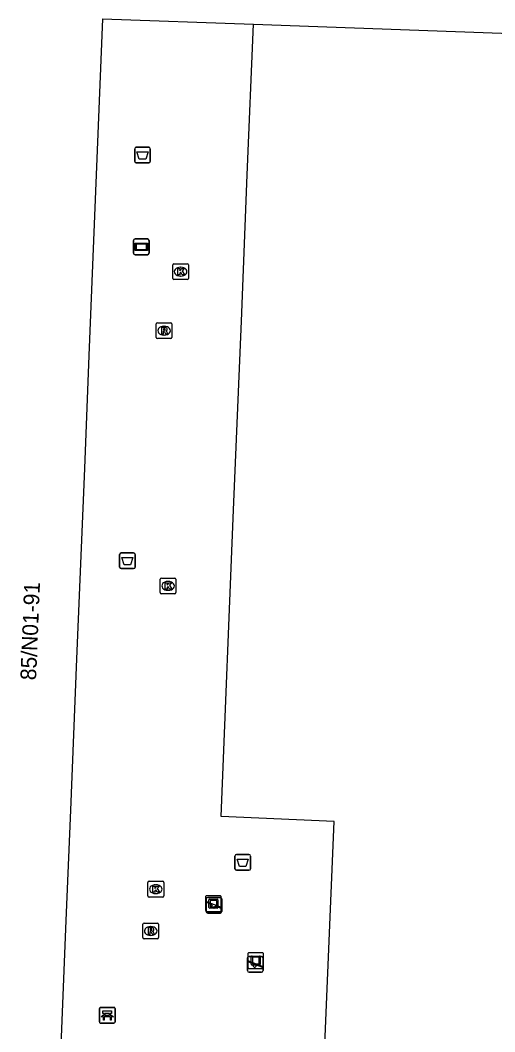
# Model space of a CAD drawing. Extents: x 160891 to 161384, y 386490 to 386907.
# Drawn here: x 161156 to 161186.2, y 386769.6 to 386833.9 of the extents above; entities that cross this region are included whole.
import ezdxf

# ---------------------------------------------------------------- set-up
doc = ezdxf.new("R2010")
doc.units = 0
for name, color, linetype in [('IMGEO_Afvalbak', 7, 'Continuous'), ('IMGEO_Bank', 7, 'Continuous'), ('IMGEO_Kolk', 7, 'Continuous'), ('IMGEO_Kunstobject', 7, 'Continuous'), ('IMGEO_Pand', 7, 'Continuous'), ('IMGEO_Pand_nummerreeks', 7, 'Continuous'), ('IMGEO_Reclamebord', 7, 'Continuous'), ('IMGEO_Rioolput', 7, 'Continuous'), ('IMGEO_Speelvoorziening', 7, 'Continuous'), ('IMGEO_Voetpad_open', 7, 'Continuous')]:
    doc.layers.add(name, color=color, linetype=linetype)

msp = doc.modelspace()

# ---------------------------------------------------------------- linework, layer by layer
at = {"layer": 'IMGEO_Afvalbak'}
for p, q in [((161163.42, 386825.803), (161164.21, 386825.803)), ((161164.21, 386825.803), (161163.42, 386825.803)), ((161163.32, 386824.903), (161163.32, 386825.703)), ((161163.32, 386825.703), (161163.32, 386824.903)), ((161164.31, 386825.703), (161164.31, 386824.903)), ((161164.31, 386824.903), (161164.31, 386825.703)), ((161164.21, 386824.803), (161163.42, 386824.803)), ((161163.42, 386824.803), (161164.21, 386824.803)), ((161162.36, 386799.115), (161162.36, 386799.915)), ((161162.36, 386799.915), (161162.36, 386799.115)), ((161162.46, 386800.015), (161163.25, 386800.015)), ((161163.25, 386800.015), (161162.46, 386800.015)), ((161163.35, 386799.915), (161163.35, 386799.115)), ((161163.35, 386799.115), (161163.35, 386799.915)), ((161163.25, 386799.015), (161162.46, 386799.015)), ((161162.46, 386799.015), (161163.25, 386799.015)), ((161169.786, 386780.845), (161170.576, 386780.845)), ((161170.576, 386780.845), (161169.786, 386780.845)), ((161169.686, 386779.945), (161169.686, 386780.745)), ((161169.686, 386780.745), (161169.686, 386779.945)), ((161170.676, 386780.745), (161170.676, 386779.945)), ((161170.676, 386779.945), (161170.676, 386780.745)), ((161170.576, 386779.845), (161169.786, 386779.845)), ((161169.786, 386779.845), (161170.576, 386779.845))]:
    msp.add_line(p, q, dxfattribs=at)
for points in [[(161163.463, 386825.517), (161164.167, 386825.517), (161164.018, 386825.047), (161163.612, 386825.047), (161163.463, 386825.517)], [(161162.503, 386799.729), (161163.207, 386799.729), (161163.058, 386799.259), (161162.652, 386799.259), (161162.503, 386799.729)], [(161169.829, 386780.559), (161170.533, 386780.559), (161170.384, 386780.089), (161169.978, 386780.089), (161169.829, 386780.559)]]:
    msp.add_lwpolyline(points, dxfattribs=at)
for centre, start, end in [((161163.42, 386825.703), 90, 180), ((161163.42, 386825.703), 90, 180), ((161164.21, 386825.703), 0, 90), ((161164.21, 386825.703), 360, 90), ((161163.42, 386824.903), 180, 270), ((161163.42, 386824.903), 180, 270), ((161164.21, 386824.903), 270, 0), ((161164.21, 386824.903), 270, 0), ((161162.46, 386799.915), 90, 180), ((161162.46, 386799.915), 90, 180), ((161163.25, 386799.915), 0, 90), ((161163.25, 386799.915), 360, 90), ((161162.46, 386799.115), 180, 270), ((161162.46, 386799.115), 180, 270), ((161163.25, 386799.115), 270, 0), ((161163.25, 386799.115), 270, 0), ((161169.786, 386780.745), 90, 180), ((161169.786, 386780.745), 90, 180), ((161170.576, 386780.745), 0, 90), ((161170.576, 386780.745), 360, 90), ((161169.786, 386779.945), 180, 270), ((161169.786, 386779.945), 180, 270), ((161170.576, 386779.945), 270, 0), ((161170.576, 386779.945), 270, 0)]:
    msp.add_arc(centre, 0.1, start, end, dxfattribs=at)
at = {"layer": 'IMGEO_Bank'}
for p, q in [((161161.148, 386771.132), (161161.989, 386771.132)), ((161161.989, 386771.132), (161161.148, 386771.132)), ((161161.073, 386770.207), (161161.073, 386771.048)), ((161161.073, 386771.048), (161161.073, 386770.207)), ((161161.77, 386770.53), (161161.377, 386770.53)), ((161161.382, 386770.638), (161161.382, 386770.744)), ((161161.426, 386770.744), (161161.426, 386770.638)), ((161161.714, 386770.75), (161161.432, 386770.75)), ((161161.432, 386770.632), (161161.714, 386770.632)), ((161161.72, 386770.638), (161161.72, 386770.744)), ((161161.764, 386770.744), (161161.764, 386770.638)), ((161162.073, 386771.057), (161162.073, 386770.216)), ((161162.073, 386770.216), (161162.073, 386771.057)), ((161161.998, 386770.132), (161161.157, 386770.132)), ((161161.157, 386770.132), (161161.998, 386770.132))]:
    msp.add_line(p, q, dxfattribs=at)
for points in [[(161161.32, 386770.53), (161161.178, 386770.53), (161161.29, 386770.632), (161161.376, 386770.632)], [(161161.376, 386770.75), (161161.29, 386770.75), (161161.29, 386770.911), (161161.853, 386770.911), (161161.853, 386770.75), (161161.77, 386770.75)], [(161161.37, 386770.523), (161161.37, 386770.316), (161161.327, 386770.316), (161161.327, 386770.523)], [(161161.77, 386770.632), (161161.853, 386770.632), (161161.965, 386770.53), (161161.826, 386770.53)], [(161161.82, 386770.523), (161161.82, 386770.316), (161161.776, 386770.316), (161161.776, 386770.523)]]:
    msp.add_lwpolyline(points, dxfattribs=at)
for centre, radius, start, end in [((161161.151, 386771.054), 0.0779, 92.4484, 184.28452), ((161161.151, 386771.054), 0.0779, 92.4484, 184.28452), ((161161.995, 386771.054), 0.0779, 2.4484, 94.28452), ((161161.995, 386771.054), 0.0779, 2.4484, 94.28452), ((161161.32, 386770.523), 0.00671, 2.89567, 87.10433), ((161161.377, 386770.523), 0.00671, 92.89567, 177.10433), ((161161.375, 386770.743), 0.00671, 2.89567, 87.10433), ((161161.375, 386770.639), 0.00671, 272.89567, 357.10433), ((161161.432, 386770.743), 0.00671, 92.89567, 177.10433), ((161161.432, 386770.639), 0.00671, 182.89567, 267.10433), ((161161.714, 386770.743), 0.00671, 2.89567, 87.10433), ((161161.714, 386770.639), 0.00671, 272.89567, 357.10433), ((161161.771, 386770.743), 0.00671, 92.89567, 177.10433), ((161161.771, 386770.639), 0.00671, 182.89567, 267.10433), ((161161.769, 386770.523), 0.00671, 2.89567, 87.10433), ((161161.826, 386770.523), 0.00671, 92.89567, 177.10433), ((161161.151, 386770.21), 0.0779, 182.4484, 274.28452), ((161161.151, 386770.21), 0.0779, 182.4484, 274.28452), ((161161.995, 386770.21), 0.0779, 272.4484, 4.28452), ((161161.995, 386770.21), 0.0779, 272.4484, 4.28452)]:
    msp.add_arc(centre, radius, start, end, dxfattribs=at)
at = {"layer": 'IMGEO_Kolk'}
for p, q in [((161165.734, 386817.465), (161165.734, 386818.317)), ((161165.809, 386818.391), (161166.661, 386818.391)), ((161166.222, 386818.171), (161166.247, 386818.171)), ((161166.735, 386818.317), (161166.735, 386817.465)), ((161166.245, 386817.611), (161166.22, 386817.611)), ((161166.661, 386817.391), (161165.809, 386817.391)), ((161164.941, 386797.493), (161164.941, 386798.345)), ((161165.016, 386798.419), (161165.868, 386798.419)), ((161165.429, 386798.199), (161165.454, 386798.199)), ((161165.942, 386798.345), (161165.942, 386797.493)), ((161165.452, 386797.639), (161165.427, 386797.639)), ((161165.868, 386797.419), (161165.016, 386797.419)), ((161164.159, 386778.217), (161164.159, 386779.069)), ((161164.234, 386779.143), (161165.086, 386779.143)), ((161164.647, 386778.923), (161164.672, 386778.923)), ((161165.16, 386779.069), (161165.16, 386778.217)), ((161164.67, 386778.363), (161164.645, 386778.363)), ((161165.086, 386778.143), (161164.234, 386778.143))]:
    msp.add_line(p, q, dxfattribs=at)
for points in [[(161165.734, 386817.465), (161165.734, 386818.317)], [(161165.809, 386818.391), (161166.661, 386818.391)], [(161166.055, 386818.091), (161166.178, 386818.091), (161166.178, 386817.94), (161166.308, 386818.091), (161166.472, 386818.091), (161166.326, 386817.94), (161166.479, 386817.691), (161166.327, 386817.691), (161166.242, 386817.855), (161166.178, 386817.788), (161166.178, 386817.691), (161166.055, 386817.691), (161166.055, 386818.091)], [(161166.735, 386818.317), (161166.735, 386817.465)], [(161166.661, 386817.391), (161165.809, 386817.391)], [(161164.941, 386797.493), (161164.941, 386798.345)], [(161165.016, 386798.419), (161165.868, 386798.419)], [(161165.942, 386798.345), (161165.942, 386797.493)], [(161165.262, 386798.119), (161165.385, 386798.119), (161165.385, 386797.968), (161165.515, 386798.119), (161165.679, 386798.119), (161165.533, 386797.968), (161165.686, 386797.719), (161165.534, 386797.719), (161165.449, 386797.883), (161165.385, 386797.816), (161165.385, 386797.719), (161165.262, 386797.719), (161165.262, 386798.119)], [(161165.868, 386797.419), (161165.016, 386797.419)], [(161164.159, 386778.217), (161164.159, 386779.069)], [(161164.234, 386779.143), (161165.086, 386779.143)], [(161164.48, 386778.843), (161164.603, 386778.843), (161164.603, 386778.692), (161164.733, 386778.843), (161164.897, 386778.843), (161164.751, 386778.692), (161164.904, 386778.443), (161164.752, 386778.443), (161164.667, 386778.607), (161164.603, 386778.54), (161164.603, 386778.443), (161164.48, 386778.443), (161164.48, 386778.843)], [(161165.16, 386779.069), (161165.16, 386778.217)], [(161165.086, 386778.143), (161164.234, 386778.143)]]:
    msp.add_lwpolyline(points, dxfattribs=at)
for centre, start, end in [((161165.811, 386818.315), 91.55205, 178.44795), ((161165.811, 386818.315), 91.55205, 178.44795), ((161166.659, 386818.315), 1.55205, 88.44795), ((161166.659, 386818.315), 1.55205, 88.44795), ((161165.811, 386817.467), 181.55205, 268.44795), ((161165.811, 386817.467), 181.55205, 268.44795), ((161166.659, 386817.467), 271.55205, 358.44795), ((161166.659, 386817.467), 271.55205, 358.44795), ((161165.018, 386798.343), 91.55205, 178.44795), ((161165.018, 386798.343), 91.55205, 178.44795), ((161165.866, 386798.343), 1.55205, 88.44795), ((161165.866, 386798.343), 1.55205, 88.44795), ((161165.018, 386797.495), 181.55205, 268.44795), ((161165.018, 386797.495), 181.55205, 268.44795), ((161165.866, 386797.495), 271.55205, 358.44795), ((161165.866, 386797.495), 271.55205, 358.44795), ((161164.236, 386779.067), 91.55205, 178.44795), ((161164.236, 386779.067), 91.55205, 178.44795), ((161165.084, 386779.067), 1.55205, 88.44795), ((161165.084, 386779.067), 1.55205, 88.44795), ((161164.236, 386778.219), 181.55205, 268.44795), ((161164.236, 386778.219), 181.55205, 268.44795), ((161165.084, 386778.219), 271.55205, 358.44795), ((161165.084, 386778.219), 271.55205, 358.44795)]:
    msp.add_arc(centre, 0.0765, start, end, dxfattribs=at)
for centre, major_axis, ratio, start_param, end_param in [((161166.221, 386817.891), (-0.387, 0.002), 0.722429, 4.712389, 7.853982), ((161166.246, 386817.891), (-0.39, 0.002), 0.717154, 1.570796, 4.712389), ((161165.428, 386797.919), (-0.387, 0.002), 0.722429, 4.712389, 7.853982), ((161165.453, 386797.919), (-0.39, 0.002), 0.717154, 1.570796, 4.712389), ((161164.646, 386778.643), (-0.387, 0.002), 0.722429, 4.712389, 7.853982), ((161164.671, 386778.643), (-0.39, 0.002), 0.717154, 1.570796, 4.712389)]:
    msp.add_ellipse(centre, major_axis=major_axis, ratio=ratio, start_param=start_param, end_param=end_param, dxfattribs=at)
at = {"layer": 'IMGEO_Kunstobject'}
for p, q in [((161168.739, 386778.223), (161167.898, 386778.223)), ((161168.739, 386778.223), (161167.898, 386778.223)), ((161167.823, 386778.139), (161167.823, 386777.298)), ((161167.823, 386778.139), (161167.823, 386777.298)), ((161168.037, 386777.487), (161168.037, 386777.961)), ((161168.087, 386778.011), (161168.561, 386778.011)), ((161168.117, 386777.911), (161168.117, 386777.537)), ((161168.511, 386777.931), (161168.137, 386777.931)), ((161168.531, 386777.537), (161168.531, 386777.911)), ((161168.611, 386777.961), (161168.611, 386777.487)), ((161168.823, 386777.307), (161168.823, 386778.148)), ((161168.823, 386777.307), (161168.823, 386778.148)), ((161167.907, 386777.223), (161168.748, 386777.223)), ((161167.907, 386777.223), (161168.748, 386777.223)), ((161168.561, 386777.437), (161168.087, 386777.437)), ((161168.137, 386777.517), (161168.511, 386777.517)), ((161170.514, 386774.521), (161170.514, 386773.68)), ((161170.514, 386774.521), (161170.514, 386773.68)), ((161171.43, 386774.605), (161170.589, 386774.605)), ((161171.43, 386774.605), (161170.589, 386774.605)), ((161170.728, 386773.869), (161170.728, 386774.343)), ((161170.778, 386774.393), (161171.252, 386774.393)), ((161171.302, 386774.343), (161171.302, 386773.869)), ((161171.514, 386773.689), (161171.514, 386774.53)), ((161171.514, 386773.689), (161171.514, 386774.53)), ((161171.252, 386773.819), (161170.778, 386773.819)), ((161170.808, 386774.293), (161170.808, 386773.919)), ((161171.202, 386774.313), (161170.828, 386774.313)), ((161170.828, 386773.899), (161171.202, 386773.899)), ((161171.222, 386773.919), (161171.222, 386774.293)), ((161170.598, 386773.605), (161171.439, 386773.605)), ((161170.598, 386773.605), (161171.439, 386773.605))]:
    msp.add_line(p, q, dxfattribs=at)
for centre, radius, start, end in [((161167.901, 386778.145), 0.0779, 92.4484, 184.28452), ((161167.901, 386778.145), 0.0779, 92.4484, 184.28452), ((161168.745, 386778.145), 0.0779, 2.4484, 94.28452), ((161168.745, 386778.145), 0.0779, 2.4484, 94.28452), ((161168.087, 386777.961), 0.05, 90, 180), ((161168.137, 386777.911), 0.02, 90, 180), ((161168.511, 386777.911), 0.02, 360, 90), ((161168.561, 386777.961), 0.05, 360, 90), ((161167.901, 386777.301), 0.0779, 182.4484, 274.28452), ((161167.901, 386777.301), 0.0779, 182.4484, 274.28452), ((161168.087, 386777.487), 0.05, 180, 270), ((161168.137, 386777.537), 0.02, 180, 270), ((161168.511, 386777.537), 0.02, 270, 0), ((161168.561, 386777.487), 0.05, 270, 0), ((161168.745, 386777.301), 0.0779, 272.4484, 4.28452), ((161168.745, 386777.301), 0.0779, 272.4484, 4.28452), ((161170.592, 386774.527), 0.0779, 92.4484, 184.28452), ((161170.592, 386774.527), 0.0779, 92.4484, 184.28452), ((161170.778, 386774.343), 0.05, 90, 180), ((161171.252, 386774.343), 0.05, 360, 90), ((161171.436, 386774.527), 0.0779, 2.4484, 94.28452), ((161171.436, 386774.527), 0.0779, 2.4484, 94.28452), ((161170.778, 386773.869), 0.05, 180, 270), ((161170.828, 386774.293), 0.02, 90, 180), ((161170.828, 386773.919), 0.02, 180, 270), ((161171.202, 386774.293), 0.02, 360, 90), ((161171.202, 386773.919), 0.02, 270, 0), ((161171.252, 386773.869), 0.05, 270, 0), ((161170.592, 386773.683), 0.0779, 182.4484, 274.28452), ((161170.592, 386773.683), 0.0779, 182.4484, 274.28452), ((161171.436, 386773.683), 0.0779, 272.4484, 4.28452), ((161171.436, 386773.683), 0.0779, 272.4484, 4.28452)]:
    msp.add_arc(centre, radius, start, end, dxfattribs=at)
at = {"layer": 'IMGEO_Pand'}
for points in [[(161161.282, 386833.963), (161160.709, 386819.875), (161160.411, 386812.554), (161160.119, 386805.384), (161159.627, 386793.285), (161159.236, 386783.673), (161158.95, 386776.656), (161158.648, 386769.233), (161158.228, 386758.915)], [(161173.519, 386722.968), (161174.331, 386742.954), (161174.605, 386749.514), (161174.625, 386750), (161174.808, 386754.38), (161175.112, 386761.653), (161175.409, 386768.77), (161176.001, 386782.954), (161168.81, 386783.258), (161169.606, 386802.752), (161170.096, 386814.751), (161170.475, 386824.04), (161170.867, 386833.628)], [(161170.867, 386833.628), (161190.117, 386832.93), (161199.627, 386832.585), (161199.621, 386832.448)]]:
    msp.add_lwpolyline(points, dxfattribs=at)
at = {"layer": 'IMGEO_Reclamebord'}
for p, q in [((161163.239, 386819.071), (161163.239, 386819.871)), ((161163.239, 386819.871), (161163.239, 386819.071)), ((161163.339, 386819.971), (161164.129, 386819.971)), ((161164.129, 386819.971), (161163.339, 386819.971)), ((161164.229, 386819.871), (161164.229, 386819.071)), ((161164.229, 386819.071), (161164.229, 386819.871)), ((161164.129, 386818.971), (161163.339, 386818.971)), ((161163.339, 386818.971), (161164.129, 386818.971))]:
    msp.add_line(p, q, dxfattribs=at)
for points in [[(161163.34, 386819.703), (161164.128, 386819.703), (161164.128, 386819.239), (161163.34, 386819.239), (161163.34, 386819.703)], [(161163.405, 386819.638), (161163.405, 386819.304), (161164.063, 386819.304), (161164.063, 386819.638), (161163.405, 386819.638)]]:
    msp.add_lwpolyline(points, dxfattribs=at)
for centre, start, end in [((161163.339, 386819.871), 90, 180), ((161163.339, 386819.871), 90, 180), ((161164.129, 386819.871), 0, 90), ((161164.129, 386819.871), 360, 90), ((161163.339, 386819.071), 180, 270), ((161163.339, 386819.071), 180, 270), ((161164.129, 386819.071), 270, 0), ((161164.129, 386819.071), 270, 0)]:
    msp.add_arc(centre, 0.1, start, end, dxfattribs=at)
at = {"layer": 'IMGEO_Rioolput'}
for p, q in [((161164.687, 386813.716), (161164.687, 386814.568)), ((161164.762, 386814.642), (161165.614, 386814.642)), ((161165.175, 386814.422), (161165.2, 386814.422)), ((161165.688, 386814.568), (161165.688, 386813.716)), ((161165.614, 386813.642), (161164.762, 386813.642)), ((161165.198, 386813.862), (161165.173, 386813.862)), ((161163.839, 386775.562), (161163.839, 386776.414)), ((161163.914, 386776.488), (161164.766, 386776.488)), ((161164.327, 386776.268), (161164.352, 386776.268)), ((161164.84, 386776.414), (161164.84, 386775.562)), ((161164.35, 386775.708), (161164.325, 386775.708)), ((161164.766, 386775.488), (161163.914, 386775.488))]:
    msp.add_line(p, q, dxfattribs=at)
for points in [[(161164.687, 386813.716), (161164.687, 386814.568)], [(161164.762, 386814.642), (161165.614, 386814.642)], [(161165.276, 386814.34), (161165.024, 386814.342), (161165.024, 386813.942)], [(161165.202, 386814.261), (161165.148, 386814.261), (161165.148, 386814.18)], [(161165.688, 386814.568), (161165.688, 386813.716)], [(161165.614, 386813.642), (161164.762, 386813.642)], [(161165.024, 386813.942), (161165.148, 386813.942), (161165.148, 386814.104), (161165.159, 386814.104)], [(161165.148, 386814.18), (161165.2, 386814.18)], [(161165.206, 386814.075), (161165.277, 386813.942), (161165.417, 386813.942), (161165.352, 386814.068)], [(161163.839, 386775.562), (161163.839, 386776.414)], [(161163.914, 386776.488), (161164.766, 386776.488)], [(161164.84, 386776.414), (161164.84, 386775.562)], [(161164.428, 386776.186), (161164.176, 386776.188), (161164.176, 386775.788)], [(161164.176, 386775.788), (161164.3, 386775.788), (161164.3, 386775.95), (161164.311, 386775.95)], [(161164.354, 386776.107), (161164.3, 386776.107), (161164.3, 386776.026)], [(161164.3, 386776.026), (161164.352, 386776.026)], [(161164.358, 386775.921), (161164.429, 386775.788), (161164.569, 386775.788), (161164.504, 386775.914)], [(161164.766, 386775.488), (161163.914, 386775.488)]]:
    msp.add_lwpolyline(points, dxfattribs=at)
for centre, radius, start, end in [((161164.764, 386814.566), 0.0765, 91.55205, 178.44795), ((161164.764, 386814.566), 0.0765, 91.55205, 178.44795), ((161165.208, 386814.165), 0.0964, 77.00612, 93.18647), ((161165.222, 386814.222), 0.0378, 276.66336, 79.67722), ((161165.275, 386814.23), 0.109, 350.36119, 89.41601), ((161165.273, 386814.23), 0.112, 277.58423, 350.98172), ((161165.612, 386814.566), 0.0765, 1.55205, 88.44795), ((161165.612, 386814.566), 0.0765, 1.55205, 88.44795), ((161164.764, 386813.718), 0.0765, 181.55205, 268.44795), ((161164.764, 386813.718), 0.0765, 181.55205, 268.44795), ((161165.158, 386814.051), 0.0533, 26.02933, 88.69889), ((161165.184, 386814.369), 0.19, 274.7715, 282.96867), ((161165.257, 386814.015), 0.108, 29.51342, 73.79051), ((161165.612, 386813.718), 0.0765, 271.55205, 358.44795), ((161165.612, 386813.718), 0.0765, 271.55205, 358.44795), ((161163.916, 386776.412), 0.0765, 91.55205, 178.44795), ((161163.916, 386776.412), 0.0765, 91.55205, 178.44795), ((161164.764, 386776.412), 0.0765, 1.55205, 88.44795), ((161164.764, 386776.412), 0.0765, 1.55205, 88.44795), ((161164.31, 386775.897), 0.0533, 26.02933, 88.69889), ((161164.336, 386776.215), 0.19, 274.7715, 282.96867), ((161164.36, 386776.011), 0.0964, 77.00612, 93.18647), ((161164.374, 386776.068), 0.0378, 276.66336, 79.67722), ((161164.427, 386776.076), 0.109, 350.36119, 89.41601), ((161164.425, 386776.076), 0.112, 277.58423, 350.98172), ((161164.409, 386775.861), 0.108, 29.51342, 73.79051), ((161163.916, 386775.564), 0.0765, 181.55205, 268.44795), ((161163.916, 386775.564), 0.0765, 181.55205, 268.44795), ((161164.764, 386775.564), 0.0765, 271.55205, 358.44795), ((161164.764, 386775.564), 0.0765, 271.55205, 358.44795)]:
    msp.add_arc(centre, radius, start, end, dxfattribs=at)
for centre, major_axis, ratio, start_param, end_param in [((161165.174, 386814.142), (-0.387, 0.002), 0.722429, 4.712389, 7.853982), ((161165.199, 386814.142), (-0.39, 0.002), 0.717154, 1.570796, 4.712389), ((161164.326, 386775.988), (-0.387, 0.002), 0.722429, 4.712389, 7.853982), ((161164.351, 386775.988), (-0.39, 0.002), 0.717154, 1.570796, 4.712389)]:
    msp.add_ellipse(centre, major_axis=major_axis, ratio=ratio, start_param=start_param, end_param=end_param, dxfattribs=at)
at = {"layer": 'IMGEO_Speelvoorziening'}
for p, q in [((161167.86, 386777.22), (161167.86, 386778.02)), ((161167.86, 386778.02), (161167.86, 386777.22)), ((161168.243, 386777.648), (161167.904, 386777.785)), ((161167.929, 386777.845), (161168.805, 386777.492)), ((161167.96, 386778.12), (161168.75, 386778.12)), ((161168.75, 386778.12), (161167.96, 386778.12)), ((161168.781, 386777.432), (161168.441, 386777.569)), ((161168.85, 386778.02), (161168.85, 386777.22)), ((161168.85, 386777.22), (161168.85, 386778.02)), ((161168.75, 386777.12), (161167.96, 386777.12)), ((161167.96, 386777.12), (161168.75, 386777.12)), ((161170.583, 386774.368), (161171.373, 386774.368)), ((161171.373, 386774.368), (161170.583, 386774.368)), ((161170.483, 386773.468), (161170.483, 386774.268)), ((161170.483, 386774.268), (161170.483, 386773.468)), ((161170.866, 386773.896), (161170.527, 386774.033)), ((161170.552, 386774.093), (161171.428, 386773.74)), ((161171.404, 386773.68), (161171.064, 386773.817)), ((161171.473, 386774.268), (161171.473, 386773.468)), ((161171.473, 386773.468), (161171.473, 386774.268)), ((161171.373, 386773.368), (161170.583, 386773.368)), ((161170.583, 386773.368), (161171.373, 386773.368))]:
    msp.add_line(p, q, dxfattribs=at)
for centre, radius, start, end in [((161167.96, 386778.02), 0.1, 90, 180), ((161167.96, 386778.02), 0.1, 90, 180), ((161167.917, 386777.815), 0.0327, 68.07798, 248.07798), ((161168.322, 386777.558), 0.12, 130.99278, 5.16318), ((161168.75, 386778.02), 0.1, 0, 90), ((161168.75, 386778.02), 0.1, 360, 90), ((161167.96, 386777.22), 0.1, 180, 270), ((161167.96, 386777.22), 0.1, 180, 270), ((161168.75, 386777.22), 0.1, 270, 0), ((161168.75, 386777.22), 0.1, 270, 0), ((161168.793, 386777.462), 0.0327, 248.07798, 68.07798), ((161170.583, 386774.268), 0.1, 90, 180), ((161170.583, 386774.268), 0.1, 90, 180), ((161171.373, 386774.268), 0.1, 0, 90), ((161171.373, 386774.268), 0.1, 360, 90), ((161170.54, 386774.063), 0.0327, 68.07798, 248.07798), ((161170.945, 386773.806), 0.12, 130.99278, 5.16318), ((161171.416, 386773.71), 0.0327, 248.07798, 68.07798), ((161170.583, 386773.468), 0.1, 180, 270), ((161170.583, 386773.468), 0.1, 180, 270), ((161171.373, 386773.468), 0.1, 270, 0), ((161171.373, 386773.468), 0.1, 270, 0)]:
    msp.add_arc(centre, radius, start, end, dxfattribs=at)
at = {"layer": 'IMGEO_Voetpad_open'}
msp.add_lwpolyline([(161161.282, 386833.963), (161170.867, 386833.628)], dxfattribs=at)

# ---------------------------------------------------------------- texts
at = {"layer": 'IMGEO_Pand_nummerreeks'}
msp.add_text('85/N01-91', height=1, rotation=87.66969, dxfattribs=at).set_placement((161157.049, 386791.91))

doc.saveas('drawing.dxf')
